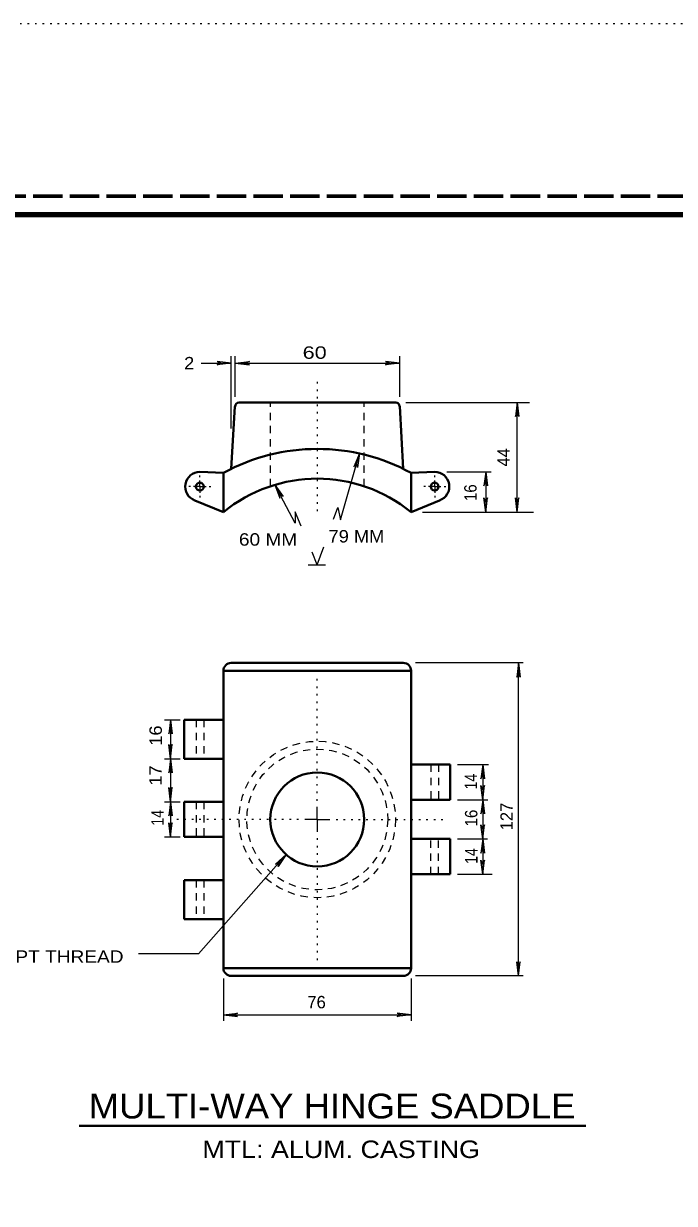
# Model space of a CAD drawing. Extents: x 312583 to 312854, y 144419 to 144597.
# Drawn here: x 312725.6 to 312765.5, y 144524.5 to 144596.8 of the extents above; entities that cross this region are included whole.
import ezdxf
from ezdxf.enums import TextEntityAlignment as Align

# ---------------------------------------------------------------- set-up
doc = ezdxf.new("R2010")
doc.units = 0
doc.header["$LTSCALE"] = 0.3
for name, pattern in [('DOTTED', [1.5, 0.3, -1.2]), ('LONG_DASHED', [7.5, 6, -1.5]), ('SHORT_DASHED', [2.7, 1.5, -1.2])]:
    doc.linetypes.add(name, pattern=pattern)
for name, color, linetype, lineweight in [('1', 7, 'Continuous', 40), ('2', 7, 'Continuous', 13), ('62', 7, 'DOTTED', 13), ('63', 7, 'LONG_DASHED', 60)]:
    doc.layers.add(name, color=color, linetype=linetype, lineweight=lineweight)

msp = doc.modelspace()

# ---------------------------------------------------------------- linework, layer by layer
at = {"layer": '1', "linetype": 'DOTTED', "lineweight": 13}
msp.add_line((312743.6108, 144574.8373), (312743.6108, 144566.8256), dxfattribs=at)
at = {"layer": '1'}
for p, q in [((312738.5661, 144573.3423), (312738.3361, 144569.5166)), ((312738.8191, 144573.58), (312748.4178, 144573.58)), ((312748.6554, 144573.35), (312748.8778, 144569.5166)), ((312737.8608, 144569.2636), (312736.4194, 144569.3326)), ((312737.8608, 144566.8716), (312737.8608, 144569.2636)), ((312737.8608, 144566.8716), (312736.1128, 144567.5846)), ((312749.3608, 144566.8716), (312751.1011, 144567.5846)), ((312738.3361, 144557.6256), (312748.8778, 144557.6256)), ((312737.8608, 144557.1503), (312737.8608, 144538.942)), ((312737.8608, 144557.1503), (312749.3608, 144557.1503)), ((312749.3608, 144557.1503), (312749.3608, 144538.942)), ((312735.4611, 144554.1526), (312735.4611, 144551.7606)), ((312737.8608, 144554.1526), (312735.4611, 144554.1526)), ((312737.8608, 144551.7606), (312735.4611, 144551.7606)), ((312749.3608, 144551.4003), (312751.7528, 144551.4003)), ((312751.7528, 144551.4003), (312751.7528, 144549.246)), ((312737.8608, 144549.1233), (312735.4611, 144549.1233)), ((312735.4611, 144549.1233), (312735.4611, 144546.969)), ((312749.3608, 144549.246), (312751.7528, 144549.246)), ((312737.8608, 144546.969), (312735.4611, 144546.969)), ((312749.3608, 144546.8463), (312751.7528, 144546.8463)), ((312751.7528, 144544.692), (312751.7528, 144546.8463)), ((312737.8608, 144544.3316), (312735.4611, 144544.3316)), ((312735.4611, 144541.932), (312735.4611, 144544.3316)), ((312749.3608, 144544.692), (312751.7528, 144544.692)), ((312737.8608, 144541.932), (312735.4611, 144541.932)), ((312737.8608, 144538.942), (312749.3608, 144538.942)), ((312738.3361, 144538.459), (312748.8778, 144538.459))]:
    msp.add_line(p, q, dxfattribs=at)
at = {"layer": '1', "linetype": 'SHORT_DASHED', "lineweight": 25}
for p, q in [((312740.7358, 144568.451), (312740.7358, 144573.58)), ((312746.4858, 144568.451), (312746.4858, 144573.58)), ((312736.1818, 144554.1526), (312736.1818, 144551.7606)), ((312736.6571, 144554.1526), (312736.6571, 144551.7606)), ((312750.5568, 144551.4003), (312750.5568, 144549.246)), ((312751.0398, 144551.4003), (312751.0398, 144549.246)), ((312736.1818, 144549.1233), (312736.1818, 144546.969)), ((312736.6571, 144549.1233), (312736.6571, 144546.969)), ((312750.5568, 144544.692), (312750.5568, 144546.8463)), ((312751.0398, 144544.692), (312751.0398, 144546.8463)), ((312736.1818, 144544.3316), (312736.1818, 144541.932)), ((312736.6571, 144544.3316), (312736.6571, 144541.932))]:
    msp.add_line(p, q, dxfattribs=at)
at = {"layer": '1', "lineweight": 158}
msp.add_lwpolyline([(312616.5, 144423.1446), (312616.5, 144585.0846), (312849, 144585.0846)], dxfattribs=at)
at = {"layer": '1'}
msp.add_lwpolyline([(312749.3608, 144566.8716), (312749.3608, 144569.2636), (312750.7944, 144569.3326)], dxfattribs=at)
for centre, radius in [((312736.4175, 144568.428), 0.2396), ((312750.7964, 144568.428), 0.2396), ((312743.6069, 144548.0423), 2.875)]:
    msp.add_circle(centre, radius, dxfattribs=at)
at = {"layer": '1', "linetype": 'SHORT_DASHED', "lineweight": 25}
for radius in [4.7917, 4.3125]:
    msp.add_circle((312743.6069, 144548.0423), radius, dxfattribs=at)
at = {"layer": '1'}
for centre, radius, start, end in [((312738.8172, 144573.3366), 0.2396, 90, 180), ((312748.4141, 144573.3366), 0.2396, 3.34745, 90), ((312743.6069, 144558.7565), 11.9792, 61.31051, 118.68949), ((312743.6069, 144558.7565), 11.9792, 61.31051, 118.68949), ((312736.4209, 144568.428), 0.9008, 90, 250.00754), ((312743.6069, 144559.8106), 9.1042, 50.82773, 129.17227), ((312743.6069, 144559.8106), 9.1042, 50.82773, 129.17227), ((312750.7929, 144568.428), 0.9008, 289.99246, 90), ((312738.3361, 144557.1465), 0.4792, 90, 180), ((312748.8778, 144557.1465), 0.4792, 0, 90), ((312738.3361, 144538.9381), 0.4792, 180, 270), ((312748.8778, 144538.9381), 0.4792, 270, 0)]:
    msp.add_arc(centre, radius, start, end, dxfattribs=at)
at = {"layer": '2'}
for p, q in [((312737.4698, 144576.0946), (312737.7458, 144575.9873)), ((312738.3361, 144575.9873), (312737.4698, 144576.0946)), ((312738.3361, 144571.9853), (312738.3361, 144576.4243)), ((312738.5814, 144573.9173), (312738.5814, 144576.4243)), ((312738.5814, 144575.9873), (312739.4478, 144576.0946)), ((312739.4478, 144576.0946), (312739.1718, 144575.9873)), ((312747.7891, 144576.0946), (312748.0651, 144575.9873)), ((312748.6554, 144575.9873), (312747.7891, 144576.0946)), ((312748.6554, 144573.9173), (312748.6554, 144576.4243)), ((312736.5038, 144575.9873), (312738.3361, 144575.9873)), ((312737.4698, 144575.88), (312737.7458, 144575.9873)), ((312738.3361, 144575.9873), (312737.4698, 144575.88)), ((312738.5814, 144575.9873), (312748.6554, 144575.9873)), ((312738.5814, 144575.9873), (312739.4478, 144575.88)), ((312739.4478, 144575.88), (312739.1718, 144575.9873)), ((312747.7891, 144575.88), (312748.0651, 144575.9873)), ((312748.6554, 144575.9873), (312747.7891, 144575.88)), ((312749.0388, 144573.58), (312756.5981, 144573.58)), ((312755.8544, 144573.58), (312755.7471, 144572.7136)), ((312755.8544, 144566.8716), (312755.8544, 144573.58)), ((312755.8544, 144573.58), (312755.9618, 144572.7136)), ((312755.7471, 144572.7136), (312755.8544, 144572.9896)), ((312755.9618, 144572.7136), (312755.8544, 144572.9896)), ((312746.1944, 144570.452), (312745.8571, 144569.647)), ((312746.1944, 144570.452), (312746.0641, 144569.5933)), ((312745.8571, 144569.647), (312746.0334, 144569.8846)), ((312746.0641, 144569.5933), (312746.0334, 144569.8846)), ((312736.4194, 144568.428), (312736.4194, 144568.8113)), ((312750.8021, 144568.428), (312750.8021, 144568.8113)), ((312751.5458, 144569.3326), (312754.2674, 144569.3326)), ((312753.9224, 144569.3326), (312753.8151, 144568.4663)), ((312753.9224, 144569.3326), (312753.9224, 144566.8716)), ((312753.9224, 144569.3326), (312754.0298, 144568.4663)), ((312736.4194, 144568.428), (312736.0361, 144568.428)), ((312736.4194, 144568.428), (312736.8028, 144568.428)), ((312736.4194, 144568.428), (312736.4194, 144568.0446)), ((312741.0041, 144568.5353), (312741.3184, 144567.7226)), ((312741.0041, 144568.5353), (312741.5101, 144567.8223)), ((312750.8021, 144568.428), (312750.4188, 144568.428)), ((312750.8021, 144568.428), (312751.1854, 144568.428)), ((312750.8021, 144568.428), (312750.8021, 144568.0446)), ((312753.8151, 144568.4663), (312753.9224, 144568.7423)), ((312754.0298, 144568.4663), (312753.9224, 144568.7423)), ((312741.3184, 144567.7226), (312741.2801, 144568.014)), ((312741.5101, 144567.8223), (312741.2801, 144568.014)), ((312753.8151, 144567.738), (312753.9224, 144567.462)), ((312753.9224, 144566.8716), (312753.8151, 144567.738)), ((312754.0298, 144567.738), (312753.9224, 144567.462)), ((312753.9224, 144566.8716), (312754.0298, 144567.738)), ((312755.7471, 144567.738), (312755.8544, 144567.462)), ((312755.8544, 144566.8716), (312755.7471, 144567.738)), ((312755.9618, 144567.738), (312755.8544, 144567.462)), ((312755.8544, 144566.8716), (312755.9618, 144567.738)), ((312742.6218, 144566.0053), (312742.2614, 144566.8793)), ((312744.5998, 144566.427), (312744.8604, 144567.1476)), ((312750.0508, 144566.8716), (312756.8434, 144566.8716)), ((312743.6108, 144563.6286), (312744.0094, 144564.748)), ((312743.6108, 144563.6286), (312743.2888, 144564.403)), ((312743.0588, 144563.6286), (312744.1091, 144563.6286)), ((312756.2148, 144557.6256), (312749.6214, 144557.6256)), ((312755.9311, 144557.6256), (312755.8238, 144556.7593)), ((312755.9311, 144538.459), (312755.9311, 144557.6256)), ((312755.9311, 144557.6256), (312756.0384, 144556.7593)), ((312755.8238, 144556.7593), (312755.9311, 144557.0353)), ((312756.0384, 144556.7593), (312755.9311, 144557.0353)), ((312734.2498, 144554.1526), (312735.2004, 144554.1526)), ((312734.6178, 144554.1526), (312734.5104, 144553.2863)), ((312734.6178, 144554.1526), (312734.6178, 144551.7606)), ((312734.6178, 144554.1526), (312734.7251, 144553.2863)), ((312734.5104, 144553.2863), (312734.6178, 144553.5623)), ((312734.7251, 144553.2863), (312734.6178, 144553.5623)), ((312734.5104, 144552.627), (312734.6178, 144552.351)), ((312734.6178, 144551.7606), (312734.5104, 144552.627)), ((312734.7251, 144552.627), (312734.6178, 144552.351)), ((312734.6178, 144551.7606), (312734.7251, 144552.627)), ((312734.2498, 144551.7606), (312735.2004, 144551.7606)), ((312734.6178, 144551.7606), (312734.5104, 144550.8942)), ((312734.6178, 144551.7606), (312734.7251, 144550.8942)), ((312734.5104, 144550.8942), (312734.6178, 144551.1702)), ((312734.7251, 144550.8942), (312734.6178, 144551.1702)), ((312752.2051, 144551.4003), (312754.0988, 144551.4003)), ((312753.7385, 144551.4003), (312753.6311, 144550.534)), ((312753.6311, 144550.534), (312753.7385, 144550.81)), ((312753.7385, 144551.4003), (312753.7385, 144549.246)), ((312753.7385, 144551.4003), (312753.8458, 144550.534)), ((312753.8458, 144550.534), (312753.7385, 144550.81)), ((312753.6311, 144550.1124), (312753.7385, 144549.8364)), ((312753.7385, 144549.246), (312753.6311, 144550.1124)), ((312753.8458, 144550.1124), (312753.7385, 144549.8364)), ((312753.7385, 144549.246), (312753.8458, 144550.1124)), ((312734.5104, 144549.9896), (312734.6178, 144549.7136)), ((312734.6178, 144549.1233), (312734.5104, 144549.9896)), ((312734.7251, 144549.9896), (312734.6178, 144549.7136)), ((312734.6178, 144549.1233), (312734.7251, 144549.9896)), ((312734.2498, 144549.1233), (312735.2004, 144549.1233)), ((312734.6178, 144549.1233), (312734.5104, 144548.2569)), ((312734.6178, 144549.1233), (312734.7251, 144548.2569)), ((312743.6108, 144548.0423), (312743.6108, 144548.809)), ((312752.2051, 144549.246), (312754.0604, 144549.246)), ((312753.7385, 144549.246), (312753.6311, 144548.3796)), ((312753.6311, 144548.3796), (312753.7385, 144548.6556)), ((312753.7385, 144549.246), (312753.8458, 144548.3796)), ((312753.8458, 144548.3796), (312753.7385, 144548.6556)), ((312734.5104, 144548.2569), (312734.6178, 144548.5329)), ((312734.7251, 144548.2569), (312734.6178, 144548.5329)), ((312743.6108, 144548.0423), (312742.8441, 144548.0423)), ((312743.6108, 144548.0423), (312743.6108, 144547.2756)), ((312743.6108, 144548.0423), (312744.3774, 144548.0423)), ((312734.5104, 144547.8354), (312734.6178, 144547.5594)), ((312734.6178, 144546.969), (312734.5104, 144547.8354)), ((312734.7251, 144547.8354), (312734.6178, 144547.5594)), ((312734.6178, 144546.969), (312734.7251, 144547.8354)), ((312753.6311, 144547.7126), (312753.7385, 144547.4366)), ((312753.7385, 144546.8463), (312753.6311, 144547.7126)), ((312753.8458, 144547.7126), (312753.7385, 144547.4366)), ((312753.7385, 144546.8463), (312753.8458, 144547.7126)), ((312734.2498, 144546.969), (312735.2004, 144546.969)), ((312752.2051, 144546.8463), (312754.0298, 144546.8463)), ((312753.7385, 144546.8463), (312753.6311, 144545.9799)), ((312753.7385, 144546.8463), (312753.8458, 144545.9799)), ((312741.7018, 144545.888), (312741.0501, 144545.313)), ((312741.7018, 144545.888), (312741.2111, 144545.1673)), ((312753.6311, 144545.9799), (312753.7385, 144546.2559)), ((312753.8458, 144545.9799), (312753.7385, 144546.2559)), ((312741.0501, 144545.313), (312741.3108, 144545.451)), ((312741.2111, 144545.1673), (312741.3108, 144545.451)), ((312753.6311, 144545.5583), (312753.7385, 144545.2823)), ((312753.7385, 144544.692), (312753.6311, 144545.5583)), ((312753.8458, 144545.5583), (312753.7385, 144545.2823)), ((312753.7385, 144544.692), (312753.8458, 144545.5583)), ((312752.2051, 144544.692), (312754.3211, 144544.692)), ((312755.8238, 144539.3253), (312755.9311, 144539.0493)), ((312755.9311, 144538.459), (312755.8238, 144539.3253)), ((312756.0384, 144539.3253), (312755.9311, 144539.0493)), ((312755.9311, 144538.459), (312756.0384, 144539.3253)), ((312737.8608, 144538.298), (312737.8608, 144535.699)), ((312749.3608, 144538.298), (312749.3608, 144535.699)), ((312756.2148, 144538.459), (312749.6214, 144538.459)), ((312737.8608, 144536.0746), (312738.7271, 144536.182)), ((312737.8608, 144536.0746), (312749.3608, 144536.0746)), ((312737.8608, 144536.0746), (312738.7271, 144535.9673)), ((312738.7271, 144536.182), (312738.4511, 144536.0746)), ((312738.7271, 144535.9673), (312738.4511, 144536.0746)), ((312748.4944, 144536.182), (312748.7704, 144536.0746)), ((312749.3608, 144536.0746), (312748.4944, 144536.182)), ((312748.4944, 144535.9673), (312748.7704, 144536.0746)), ((312749.3608, 144536.0746), (312748.4944, 144535.9673))]:
    msp.add_line(p, q, dxfattribs=at)
at = {"layer": '2', "linetype": 'DOTTED'}
for p, q in [((312736.4194, 144569.003), (312736.4194, 144569.2253)), ((312750.8021, 144569.003), (312750.8021, 144569.2636)), ((312735.8444, 144568.428), (312735.6988, 144568.428)), ((312736.9944, 144568.428), (312737.2858, 144568.428)), ((312750.2271, 144568.428), (312749.8668, 144568.428)), ((312751.3771, 144568.428), (312751.5611, 144568.428)), ((312736.4194, 144567.853), (312736.4194, 144567.7533)), ((312750.8021, 144567.853), (312750.8021, 144567.7226)), ((312743.6108, 144549.1923), (312743.6108, 144556.859)), ((312742.4608, 144548.0423), (312734.7941, 144548.0423)), ((312744.7608, 144548.0423), (312751.5841, 144548.0423)), ((312743.6108, 144546.8923), (312743.6108, 144539.2256))]:
    msp.add_line(p, q, dxfattribs=at)
at = {"layer": '2', "lineweight": 40}
msp.add_line((312729.0186, 144529.282), (312760.0586, 144529.282), dxfattribs=at)
at = {"layer": '2'}
for points in [[(312744.8604, 144567.1476), (312745.0368, 144566.3963), (312746.1944, 144570.452)], [(312742.2614, 144566.8793), (312742.2614, 144566.1816), (312741.0041, 144568.5353)], [(312734.6178, 144551.7606), (312734.6178, 144549.1233), (312734.6178, 144546.969)], [(312753.7385, 144549.246), (312753.7385, 144546.8463), (312753.7385, 144544.692)], [(312741.7018, 144545.888), (312736.3274, 144539.8083), (312732.6675, 144539.8083)]]:
    msp.add_lwpolyline(points, dxfattribs=at)
at = {"layer": '62'}
msp.add_line((312601.2, 144596.7846), (312853.5, 144596.7846), dxfattribs=at)
at = {"layer": '63'}
msp.add_line((312851.75, 144586.2246), (312583.526, 144586.2246), dxfattribs=at)

# ---------------------------------------------------------------- texts
at = {"layer": '2'}
for s, width, p in [('60  ', 1.3, (312742.7132, 144576.2547)), ('2 ', 1.1, (312735.4503, 144575.6068)), ('60 MM', 1.15, (312738.8072, 144564.8102)), ('79 MM', 1.1, (312744.2983, 144565.0039)), ('40 MM NPT THREAD', 1.15, (312720.3775, 144539.263))]:
    msp.add_text(s, height=0.76, dxfattribs=dict(at, width=width)).set_placement(p)
for s, p in [('44', (312755.3931, 144569.6566)), ('127', (312755.5853, 144547.3723))]:
    msp.add_text(s, height=0.76, rotation=90, dxfattribs=at).set_placement(p)
for s, width, p in [('16', 0.9, (312753.3679, 144567.5487)), ('16 ', 1.1, (312734.0893, 144552.5556)), ('17 ', 1.1, (312734.0758, 144550.114)), ('14', 0.85, (312753.392, 144549.8818)), ('14', 0.85, (312734.1961, 144547.6623)), ('16', 0.9, (312753.4145, 144547.6206)), ('14', 0.85, (312753.4218, 144545.3207))]:
    msp.add_text(s, height=0.76, rotation=90, dxfattribs=dict(at, width=width)).set_placement(p)
msp.add_text('76', height=0.76, dxfattribs=at).set_placement((312742.9983, 144536.4743))
for s, height, width, p in [('MULTI-WAY HINGE SADDLE', 1.52, 1.1, (312744.5138, 144529.7287)), ('MTL: ALUM. CASTING', 1.07, 1.15, (312745.0697, 144527.3074))]:
    msp.add_text(s, height=height, dxfattribs=dict(at, width=width)).set_placement(p, align=Align.CENTER)

doc.saveas('drawing.dxf')
